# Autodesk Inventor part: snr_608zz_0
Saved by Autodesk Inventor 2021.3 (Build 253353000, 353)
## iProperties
Created: 2022-03
Part Number: snr_608zz_0
Material: Generic
Document SubType Name: Modeling
Designer: Administrator
Density: 1 g/cm^3
Appearance: Default
Title: snr_608zz_0 v1
Author: Administrator
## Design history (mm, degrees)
feature "Body1"
feature "Body2"
feature "Body3"
feature "Body4"
feature "Body5"
body "Solid1"
body "Solid2"
body "Solid3"
body "Solid4"
body "Solid5"
